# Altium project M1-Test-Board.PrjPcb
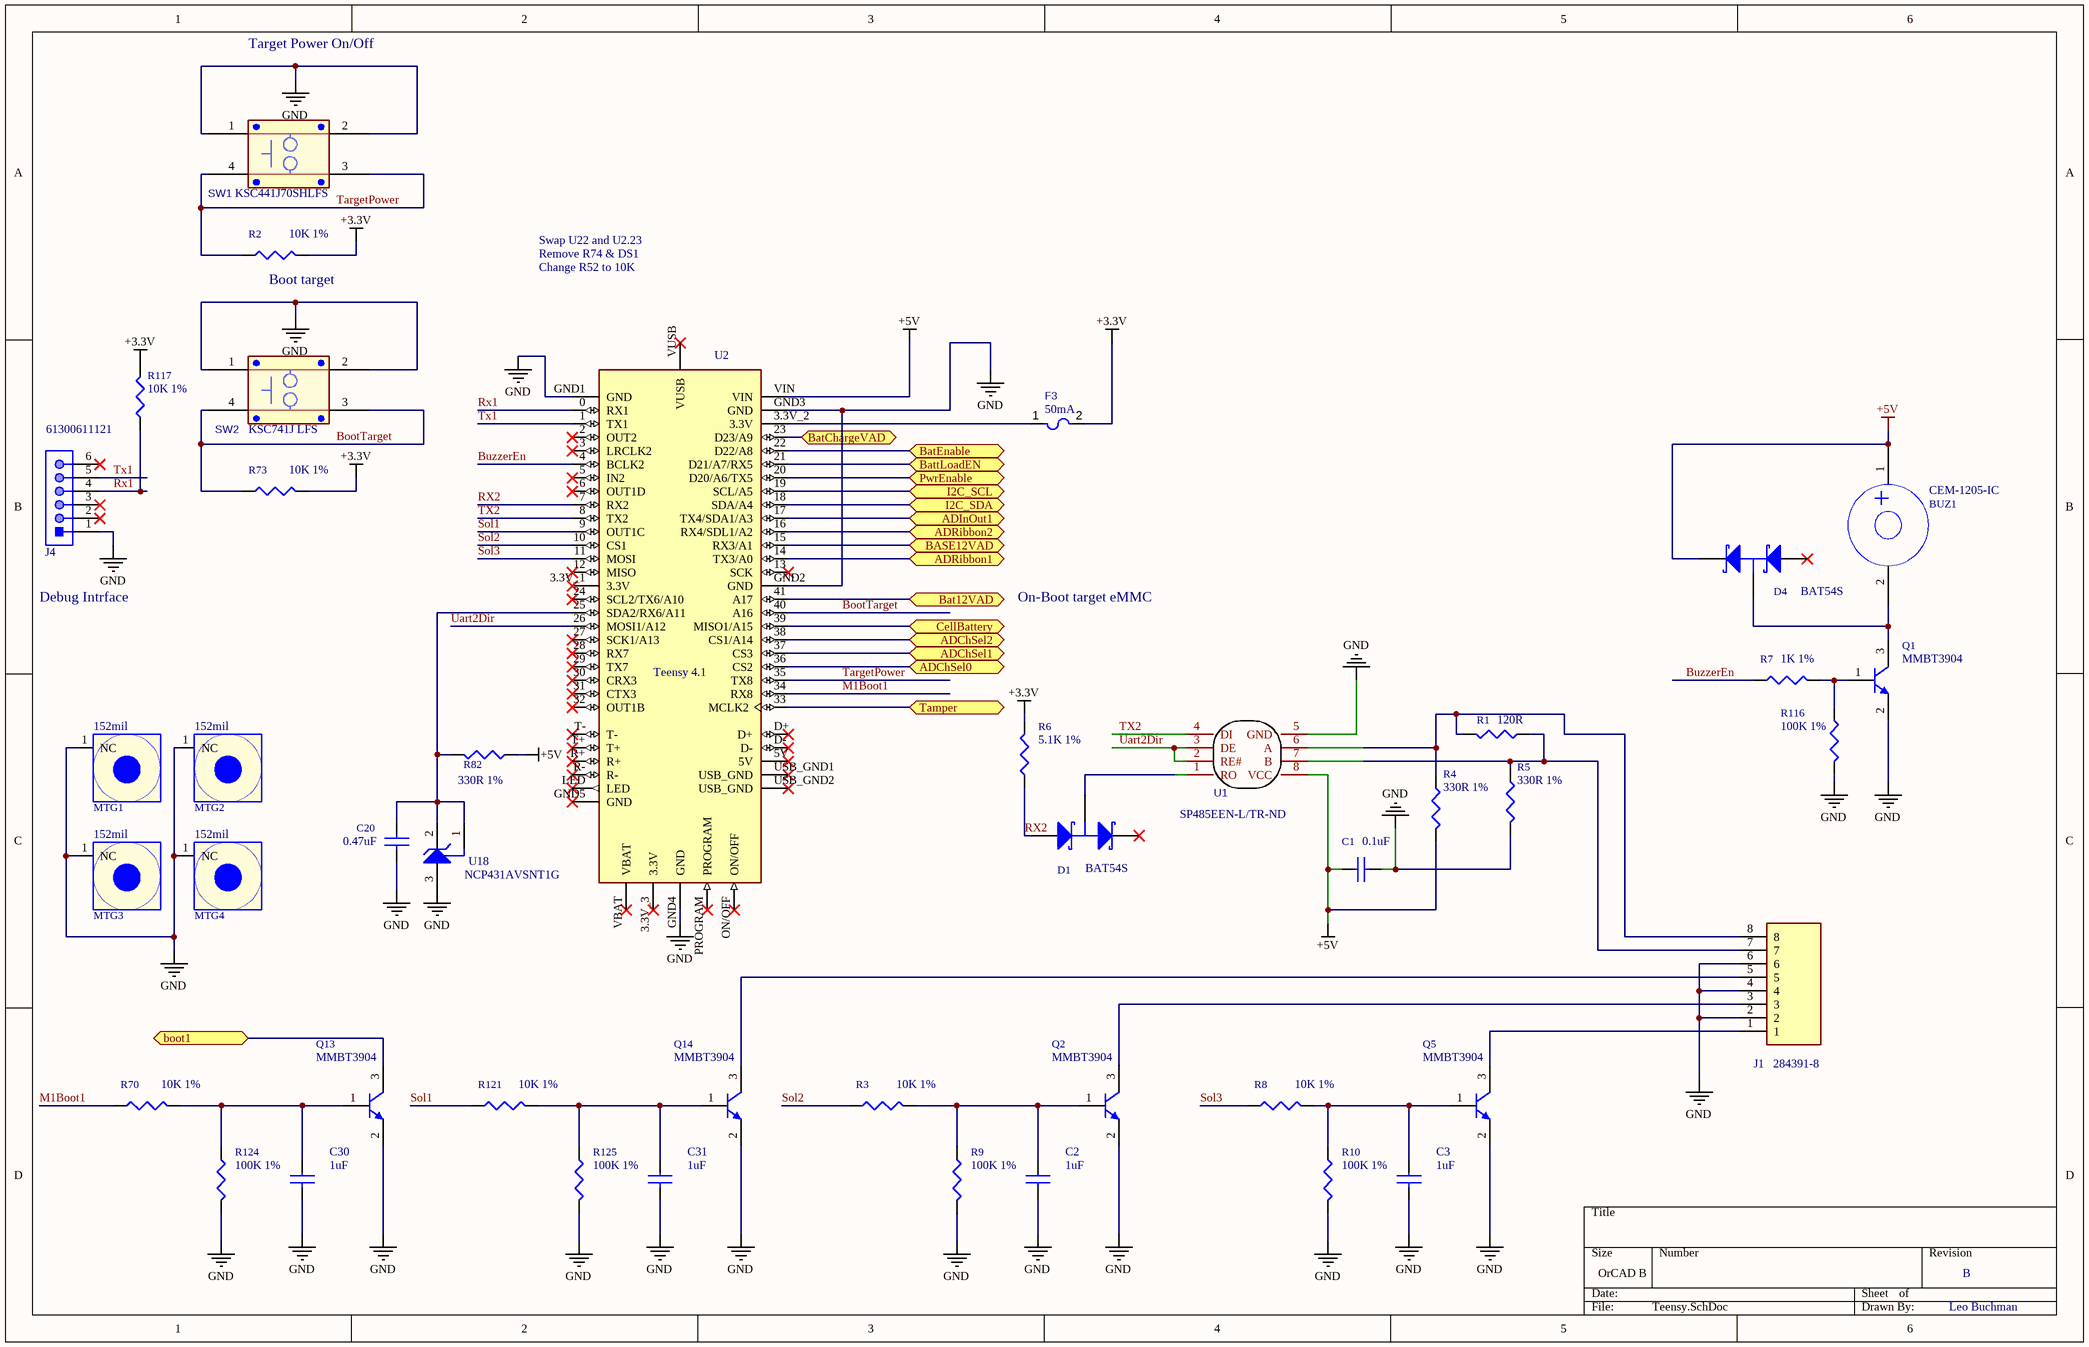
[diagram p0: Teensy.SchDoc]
4 sheets, 191 parts. Net scope: flat (ports and power ports of the same name join across sheets).
Board file: M1-Test-Board.PcbDoc
Sheets:
  Teensy.SchDoc
  RibbonCable.SchDoc
  InputOutput.SchDoc
  Power.SchDoc

## Sheet Teensy.SchDoc: M1 Test Fixture Custom Board
size OrCAD B; Author: Leo Buchman; Revision: B; SheetNumber: 1; SheetTotal: 4

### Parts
BUZ1  CEM-1205-IC  [BUZZ-MB5120C]
C1  0.1uF  [C0402]
C2  1uF  [C0402]
C3  1uF  [C0402]
C20  0.47uF  [C0402]
C30  1uF  [C0402]
C31  1uF  [C0402]
D1  BAT54S  [sot23-3]
D4  BAT54S  [sot23-3]
F3  50mA  [F0603]
J1  284391-8  [TE_284391-8]
J4  61300611121  [61300611121]
MTG1  152mil  [MNT-HOLE-169-350]  (no BOM)
MTG2  152mil  [MNT-HOLE-169-350]  (no BOM)
MTG3  152mil  [MNT-HOLE-169-350]  (no BOM)
MTG4  152mil  [MNT-HOLE-169-350]  (no BOM)
Q1  MMBT3904  [sot23-3]
Q2  MMBT3904  [sot23-3]
Q5  MMBT3904  [sot23-3]
Q13  MMBT3904  [sot23-3]
Q14  MMBT3904  [sot23-3]
R1  120R  [R0402]
R2  10K 1%  [R0402]
R3  10K 1%  [R0402]
R4  330R 1%  [R0402]
R5  330R 1%  [R0402]
R6  5.1K 1%  [R0402]
R7  1K 1%  [R0402]
R8  10K 1%  [R0402]
R9  100K 1%  [R0402]
R10  100K 1%  [R0402]
R70  10K 1%  [R0402]
R73  10K 1%  [R0402]
R82  330R 1%  [R0402]
R116  100K 1%  [R0402]
R117  10K 1%  [R0402]
R121  10K 1%  [R0402]
R124  100K 1%  [R0402]
R125  100K 1%  [R0402]
SW1  KSC441J70SHLFS  [SON4_KSC741JLFS_CNK-red]
SW2  KSC741J LFS  [SON4_KSC741JLFS_CNK-blue]
U1  SP485EEN-L/TR-ND  [NSOIC-8]
U2  Teensy 4.1  [MODULE_DEV-16771 - headers]
U18  NCP431AVSNT1G  [sot23-3]

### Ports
ADChSel0 (bidir), ADChSel1 (bidir), ADChSel2 (bidir), ADInOut1 (bidir), ADRibbon1 (bidir), ADRibbon2 (bidir), BASE12VAD (bidir), Bat12VAD (bidir), BatChargeVAD (bidir), BatEnable (bidir), BattLoadEN (bidir), boot1 (bidir), CellBattery (bidir), I2C_SCL (bidir), I2C_SDA (bidir), PwrEnable (bidir), Tamper (bidir)

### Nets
+3.3V: F3.2 R2.2 R6.2 R73.2 R117.2
+5V: BUZ1.1(POS) C1.1 D4.2(K) R4.2 R82.1 U1.8(VCC) U2.VIN
GND: C1.2 C2.2 C3.2 C20.2 C30.2 C31.2 J1.2 J1.4 J1.6 J4.1 MTG1.1(NC) MTG2.1(NC) MTG3.1(NC) MTG4.1(NC) Q1.2(E) Q2.2(E) Q5.2(E) Q13.2(E) Q14.2(E) R5.2 R9.2 R10.2 R116.2 R124.2 R125.2 SW1.1 SW1.2 SW2.1 SW2.2 U1.5(GND) U2.GND1(GND) U2.GND2(GND) U2.GND3(GND) U2.GND4(GND) U18.3(ANODE)
BootTarget: R73.1 SW2.3 SW2.4 U2.40(A16)
BuzzerEn: R7.1 U2.4(BCLK2)
M1Boot1: R70.1 U2.34(RX8)
Rx1: J4.4 R117.1 U2.0(RX1)
RX2: D1.1(A) R6.1 U2.7(RX2)
Sol1: R121.1 U2.9(OUT1C)
Sol2: R3.1 U2.10(CS1)
Sol3: R8.1 U2.11(MOSI)
TargetPower: R2.1 SW1.3 SW1.4 U2.35(TX8)
Tx1: J4.5 U2.1(TX1)
TX2: U1.4(DI) U2.8(TX2)
Uart2Dir: U1.2(RE#) U1.3(DE) U2.26(MOSI1/A12)
NetBUZ1_2: BUZ1.2(NEG) D4.3(C) Q1.3(C)
NetC2_1: C2.1 Q2.1(B) R3.2 R9.1
NetC3_1: C3.1 Q5.1(B) R8.2 R10.1
NetC20_1: C20.1 R82.2 U2.25(SDA2/RX6/A11) U18.1(REF) U18.2(CATHODE)
NetC22_1: U2.15(RX3/A1) ; port BASE12VAD
NetC23_1: U2.41(A17) ; port Bat12VAD
NetC24_1: U2.23(D23/A9) ; port BatChargeVAD
NetC30_1: C30.1 Q13.1(B) R70.2 R124.1
NetC31_1: C31.1 Q14.1(B) R121.2 R125.1
NetD1_3: D1.3(C) U1.1(RO)
NetF3_1: F3.1 U2.3.3V_2(3.3V)
NetJ1_1: J1.1 Q5.3(C)
NetJ1_3: J1.3 Q2.3(C)
NetJ1_5: J1.5 Q14.3(C)
NetJ1_7: J1.7 R1.1 R5.1 U1.7(B)
NetJ1_8: J1.8 R1.2 R4.1 U1.6(A)
NetJ5_3: U2.18(SDA/A4) ; port I2C_SDA
NetJ5_6: U2.19(SCL/A5) ; port I2C_SCL
NetJ6_8: Q13.3(C) ; port boot1
NetQ1_1: Q1.1(B) R7.2 R116.1
NetR71_2: U2.39(MISO1/A15) ; port CellBattery
NetR85_1: U2.33(MCLK2) ; port Tamper
NetR94_1: U2.20(D20/A6/TX5) ; port PwrEnable
NetR99_1: U2.21(D21/A7/RX5) ; port BattLoadEN
NetR108_1: U2.22(D22/A8) ; port BatEnable
NetR118_1: U2.14(TX3/A0) ; port ADRibbon1
NetR119_1: U2.16(RX4/SDL1/A2) ; port ADRibbon2
NetR120_1: U2.17(TX4/SDA1/A3) ; port ADInOut1
NetU2_36: U2.36(CS2) ; port ADChSel0
NetU2_37: U2.37(CS3) ; port ADChSel1
NetU2_38: U2.38(CS1/A14) ; port ADChSel2

Not connected (* = marked no-connect by the designer): D1 2(K)*; D4 1(A)*; J4 2* 3* 6*; U2 2(OUT2)* 3(LRCLK2)* 3.3V_1(3.3V)* 3.3V_3(3.3V)* 5(IN2)* 5V* 6(OUT1D)* 12(MISO)* 13(SCK)* 24(SCL2/TX6/A10)* 27(SCK1/A13)* 28(RX7)* 29(TX7)* 30(CRX3)* 31(CTX3)* 32(OUT1B)* D+* D-* GND5(GND)* LED* ON/OFF* PROGRAM* R+* R-* T+* T-* USB_GND1(USB_GND)* USB_GND2(USB_GND)* VBAT* VUSB*

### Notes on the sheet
- Target Power On/Off
- (near R2) Boot target
- Swap U22 and U2.23
- Remove R74 & DS1
- Change R52 to 10K
- Debug Intrface
- On-Boot target eMMC

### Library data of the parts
BUZ1 = Mod-0003: 12 mm, 5 Vdc, 92 dB, Through Hole, Driving Circuit, Magnetic Audio Indicator Buzzer; ADI Part Number: 3716-0001; Manufacturer: CUI Devices; Voltage: 5V; Current: 35mA; CLASS: DISCRETE; COMPSIDE: TOP; COMPLOC: [1301.000,1659.000]; COMPROT: 180; COMPGROUP: 0; COMPFIXED: NO; COMPHEIGHT: 0.000
C1 = Cap-00005: Cap Ceramic 0.1uF 50V X7R 10% Pad SMD 0402 125C Automotive T/R; Manufacturer: Murata; Manufacturer Part Number: GRT155R71H104KE01D
C2 C3 C30 C31 = Cap-00003: CAP CER 1UF 10V Y5V 0402; Manufacturer: KEMET; Manufacturer Part Number: C0402C105Z8VAC7867; Tolerance: 80%; Dielectric Material: Ceramic
C20 = Cap-00006: CAP CER 0.47UF 16V Y5V 0402; Manufacturer: Yageo; Manufacturer Part Number: CC0402ZRY5V7BB474; Tolerance: 80%; Capacitance: 470nF; Dielectric Material: Ceramic
D1 D4 = Diode-0009: DIODE SCHOTTKY 30V 150MA SOT23-3; Manufacturer: Sangdest Microelectronics; Manufacturer: ON Semiconductor / Fairchild; Recovery Time: 5ns; Package Version: Rev. 12, 03/2016; Peak Reverse Current: 2uA; Elements: 2
F3 = FEMTOASMDC005F-2: Ptc Reset Fuse 15V 50MA 0603; Manufacturer: Littelfuse; Manufacturer: Bourns; Max Current Rating: 10A; Trip Current: 150mA; Time to Trip: 100ms
J1 = CON-0011: Conn Terminal Block F 8 POS 3.5mm Solder ST T; MF: TE Connectivity
J4 = CON-0003: CONN HEADER 6 POS 2.54; Manufacturer: Wurth Electronics
MTG1-MTG4 = Hole-001: Plated
Q1 Q2 Q5 Q13 Q14 = Tran-0002: Trans GP BJT NPN 60V 0.2A 350mW Automotive 3-Pin SOT-23 T/R; Manufacturer: ON Semiconductor / Fairchild; Manufacturer: ON Semiconductor; Elements: 1; Power: 225mW; Frequency: 250MHz; Vce Max: 300mV; Max Collector Current: 200mA; Collector-emitter Voltage-Max: 400mV
R1 = Res-00013: Res Thick Film 0402 120 Ohm 1% 0.063W(1/16W) ±100ppm/C Pad SMD Automotive T/R; Manufacturer: Stackpole Electronics; Manufacturer Part Number: RMCF0402FT120R; Max Power Dissipation: 63mW; Temperature Coefficient: 100ppm/°C
R2 R3 R8 R70 R73 R117 R121 = Res-00002: Thick Film 0402 10K OHM 1% 1/16W 0402; Manufacturer: Yageo; Manufacturer Part Number: RC0402FR-0710KP; Max Power Dissipation: 63mW; Temperature Coefficient: 150ppm/°C; Power Rating: 62.5mW
R4 R5 R82 = Res-00009: Thick Film 0402 330 Ohm 1% 1/16W ±100ppm/°C Molded SMD Paper T/R; Manufacturer: Yageo; Manufacturer Part Number: AF0402FR-07330RL; Max Power Dissipation: 63mW; Power Rating: 62.5mW
R6 = Res-00004: Thick Film 0402 5.1K Ohm 1% 1/16W 0402; Manufacturer: Stackpole Electronics; Manufacturer Part Number: RMCF0402FT5K10; Max Power Dissipation: 63mW; Temperature Coefficient: 100ppm/°C; Power Rating: 62.5mW
R7 = Res-00001: Thick Film 0402 1K Ohm 1% 1/8W 0402; Manufacturer: TE Connectivity; Manufacturer Part Number: CRGP0402F1K0; Max Power Dissipation: 125mW; Temperature Coefficient: 100ppm/°C; Power Rating: 0.125W
R9 R10 R116 R124 R125 = Res-00003: Thick Film 0402 100K OHM 1% 1/16W 0402; Manufacturer: Stackpole Electronics; Manufacturer Part Number: RMCF0402FT100K; Power Rating: 62.5mW
SW1 = SW-0002: Switch Tactile N.O. SPST Round Button J-Bend; Manufacturer: ITT C&K; Actuator Material: Nylon,Polyamide,PA66; Mechanical Life: 300000Cycles; Operating Force: 5N; Max Current Rating: 50mA; Voltage Rating (DC): 32V; Illumination Type: Non-Illuminated,Illuminated; Switch Function: Off-Mom; Actuator Type: Standard; Switch Travel: 0.75mm; Actuator Length: 2.6mm; Power Rating: 1W
SW2 = SW-0001: Switch Tactile N.O. SPST Round Button J-Bend; Manufacturer: ITT C&K; Mechanical Life: 300000Cycles; Actuator Color: Blue; Operating Force: 4N; Max Current Rating: 50mA; Voltage Rating (DC): 32V; Illumination Type: Non-Illuminated; Switch Function: Off-Mom; Actuator Type: Standard; Switch Travel: 0.4mm; Actuator Length: 1.7mm; Power Rating: 1W; Ratings: IP67,Waterproof,Dust Tight
U1 = dd-0001: IC TXRX RS485 HALF DUPLEX 8SOIC; BOM_Manufacturer: EXAR; Package Display: No; Data Rate: 10Mbps; Nominal Supply Current: 900uA; Max Power Dissipation: 550mW; Operating Supply Voltage: 5V; Number of Receivers: 1; Min Supply Voltage: 4.75V; Max Supply Voltage: 5.25V; Logic Function: Transceiver; Interface: RS-422,RS-485
U2 = Mod-0004: Teensy 4.1 Development Board; Manufacturer: SparkFun
U18 = AIC-0002: V-Ref Adjustable 2.5V to 36V 100mA 3-Pin SOT-; Manufacturer: ON Semiconductor; PartNumber: TL431ACLP; Manufacturer: Texas Instruments; VO Adj(Max)(V): 36; Initial Accuracy @ 25/deg C(%): 1; SubFamily: Shunt Voltage Reference; Temp Coeff(Typ)(ppm/ degree C): 34; VO Adj(Min)(V): 2.495; Rating: Catalog; Min Iz for Regulation(uA): 600; Temp Coeff(Max)(ppm/ degree C): 92; Iout/Iz(Max)(mA): 100; Eco-Plan: Pb-Free (RoHS); Max Input Voltage: 2.525V; Min Input Voltage: 2.475V; Tolerance: 1%; Temperature Coefficient: 50ppm/°C; Cathode Current: 60uA; Reference Type: Shunt,Adjustable,Programmable

## Sheet RibbonCable.SchDoc: M1 Test Fixture Custom Board
size OrCAD B; Author: Leo Buchman; Revision: B; SheetNumber: 2; SheetTotal: 4
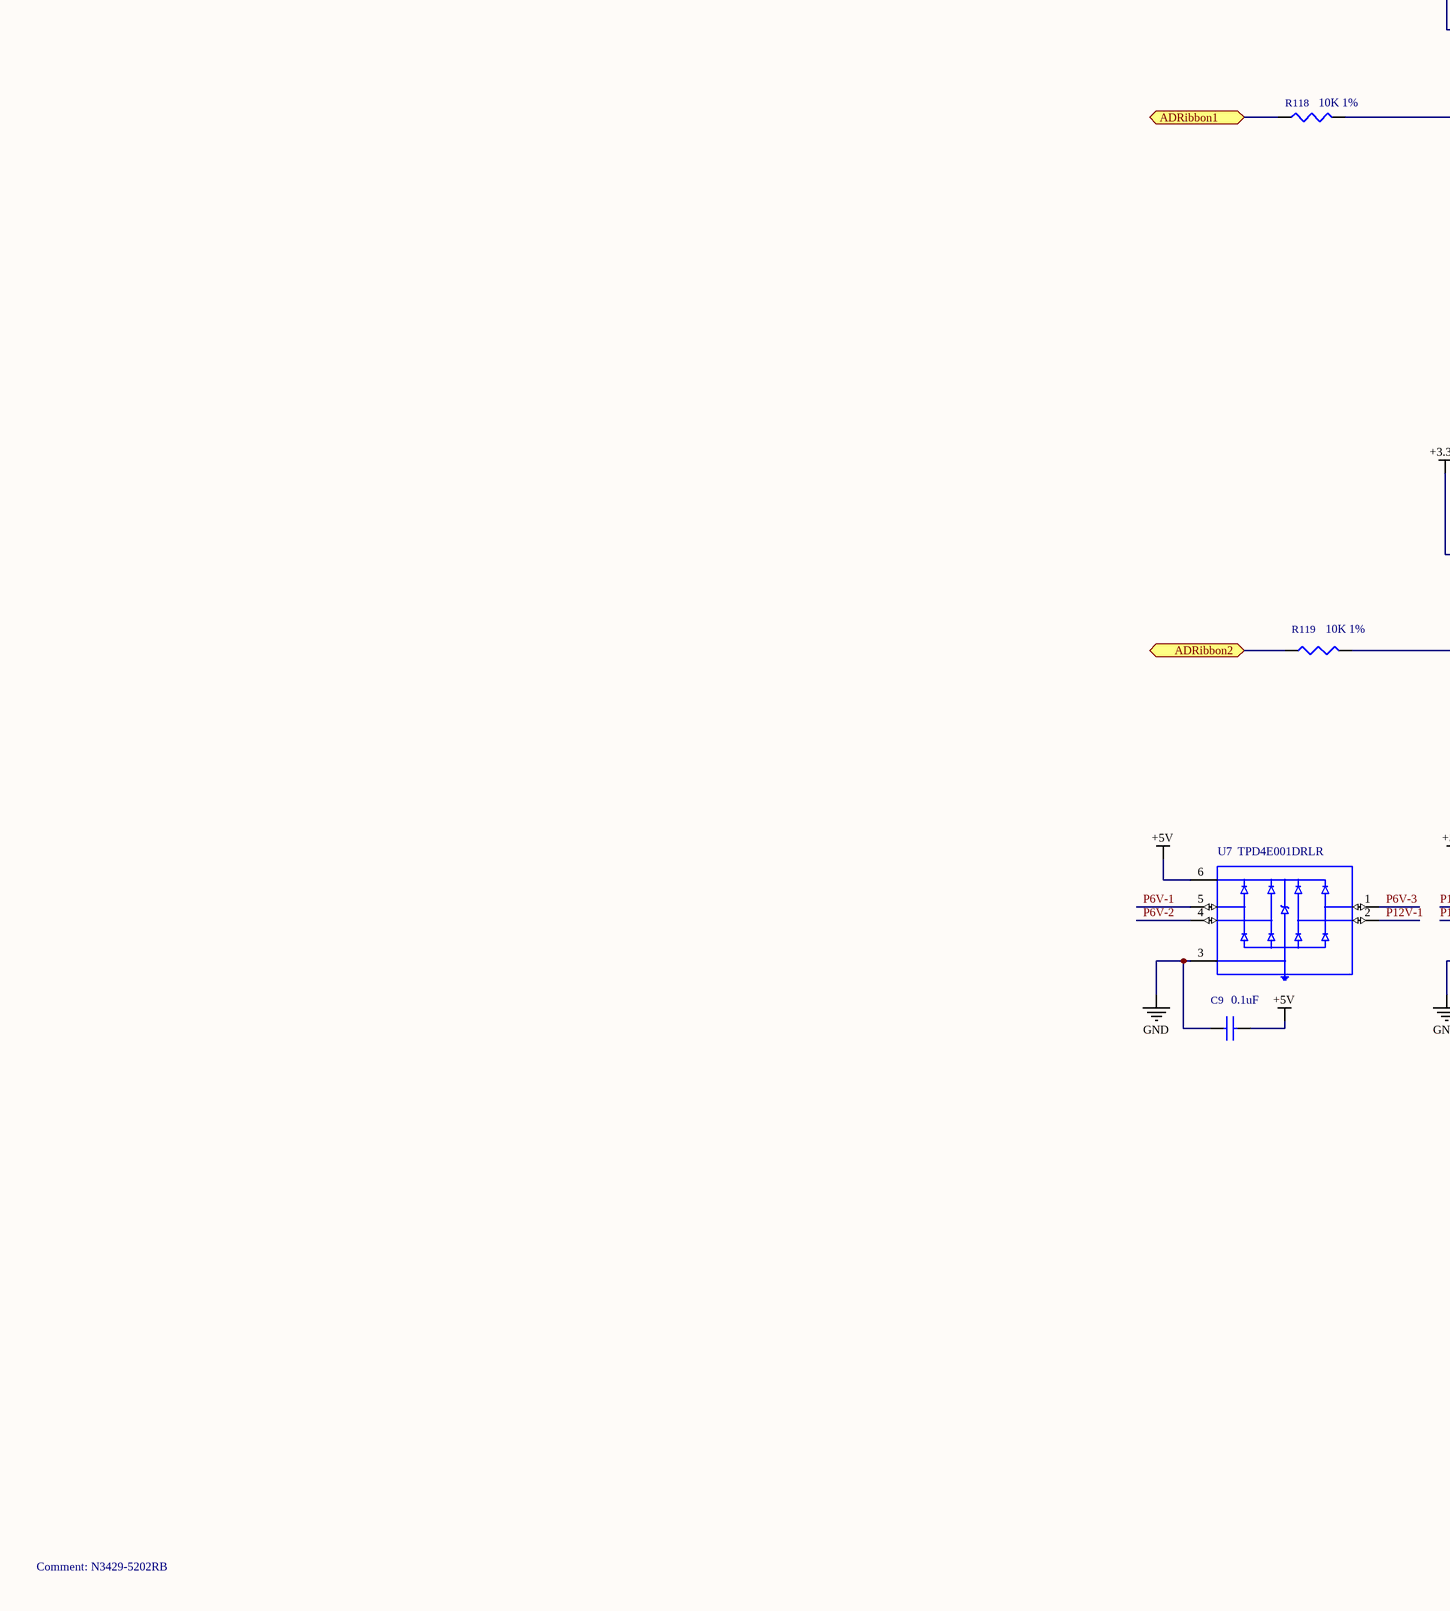
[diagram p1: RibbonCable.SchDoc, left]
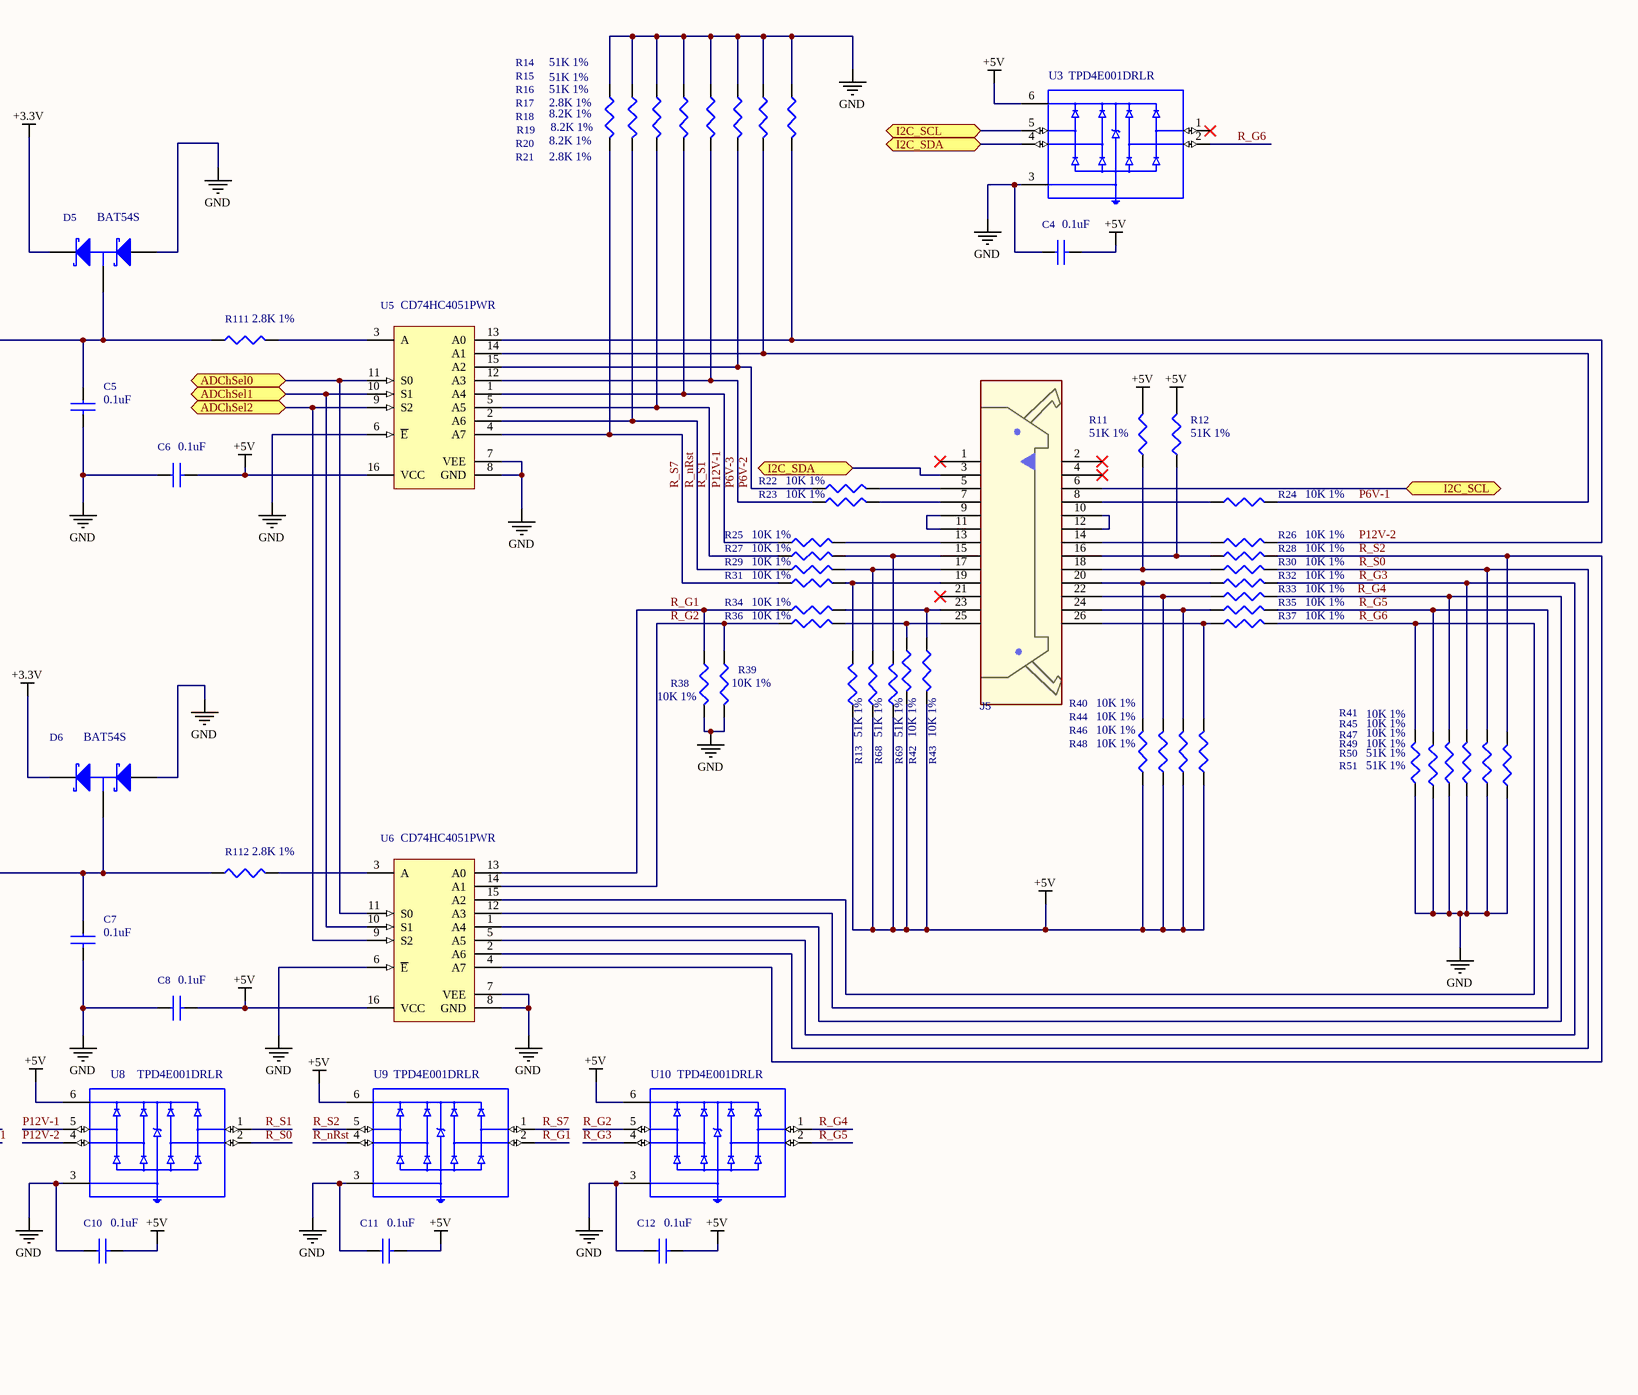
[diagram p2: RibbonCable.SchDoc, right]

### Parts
C4  0.1uF  [C0402]
C5  0.1uF  [C0402]
C6  0.1uF  [C0402]
C7  0.1uF  [C0402]
C8  0.1uF  [C0402]
C9  0.1uF  [C0402]
C10  0.1uF  [C0402]
C11  0.1uF  [C0402]
C12  0.1uF  [C0402]
D5  BAT54S  [sot23-3]
D6  BAT54S  [sot23-3]
J5  N3429-5202RB  [CONN_N3429-5202RB]
R11  51K 1%  [R0402]
R12  51K 1%  [R0402]
R13  51K 1%  [R0402]
R14  51K 1%  [R0402]
R15  51K 1%  [R0402]
R16  51K 1%  [R0402]
R17  2.8K 1%  [R0402]
R18  8.2K 1%  [R0402]
R19  8.2K 1%  [R0402]
R20  8.2K 1%  [R0402]
R21  2.8K 1%  [R0402]
R22  10K 1%  [R0402]
R23  10K 1%  [R0402]
R24  10K 1%  [R0402]
R25  10K 1%  [R0402]
R26  10K 1%  [R0402]
R27  10K 1%  [R0402]
R28  10K 1%  [R0402]
R29  10K 1%  [R0402]
R30  10K 1%  [R0402]
R31  10K 1%  [R0402]
R32  10K 1%  [R0402]
R33  10K 1%  [R0402]
R34  10K 1%  [R0402]
R35  10K 1%  [R0402]
R36  10K 1%  [R0402]
R37  10K 1%  [R0402]
R38  10K 1%  [R0402]
R39  10K 1%  [R0402]
R40  10K 1%  [R0402]
R41  10K 1%  [R0402]
R42  10K 1%  [R0402]
R43  10K 1%  [R0402]
R44  10K 1%  [R0402]
R45  10K 1%  [R0402]
R46  10K 1%  [R0402]
R47  10K 1%  [R0402]
R48  10K 1%  [R0402]
R49  10K 1%  [R0402]
R50  51K 1%  [R0402]
R51  51K 1%  [R0402]
R68  51K 1%  [R0402]
R69  51K 1%  [R0402]
R111  2.8K 1%  [R0402]
R112  2.8K 1%  [R0402]
R118  10K 1%  [R0402]
R119  10K 1%  [R0402]
U3  TPD4E001DRLR  [SOTFL50P160X60-6N]
U5  CD74HC4051PWR  [16-TSSOP-4.4mm]
U6  CD74HC4051PWR  [16-TSSOP-4.4mm]
U7  TPD4E001DRLR  [SOTFL50P160X60-6N]
U8  TPD4E001DRLR  [SOTFL50P160X60-6N]
U9  TPD4E001DRLR  [SOTFL50P160X60-6N]
U10  TPD4E001DRLR  [SOTFL50P160X60-6N]

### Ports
ADChSel0 (bidir), ADChSel1 (bidir), ADChSel2 (bidir), ADRibbon1 (bidir), ADRibbon2 (bidir), I2C_SCL (bidir), I2C_SDA (bidir)

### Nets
+3.3V: D5.2(K) D6.2(K)
+5V: C4.2 C6.2 C8.2 C9.2 C10.2 C11.2 C12.2 R11.2 R12.2 R13.1 R40.1 R42.2 R43.2 R44.1 R46.1 R48.1 R68.1 R69.1 U3.6(VCC) U5.16(VCC) U6.16(VCC) U7.6(VCC) U8.6(VCC) U9.6(VCC) U10.6(VCC)
GND: C4.1 C5.2 C6.1 C7.2 C8.1 C9.1 C10.1 C11.1 C12.1 D5.1(A) D6.1(A) R14.1 R15.1 R16.1 R17.1 R18.1 R19.1 R20.1 R21.1 R38.2 R39.2 R41.1 R45.1 R47.1 R49.1 R50.1 R51.1 U3.3(GND) U5.6(~{E}) U5.7(VEE) U5.8(GND) U6.6(~{E}) U6.7(VEE) U6.8(GND) U7.3(GND) U8.3(GND) U9.3(GND) U10.3(GND)
P6V-1: R20.2 R24.2 U5.14(A1) U7.5(IO4)
P6V-2: R19.2 R22.1 U5.15(A2) U7.4(IO3)
P6V-3: R18.2 R23.1 U5.12(A3) U7.1(IO1)
P12V-1: R17.2 R25.1 U5.1(A4) U7.2(IO2) U8.5(IO4)
P12V-2: R21.2 R26.2 U5.13(A0) U8.4(IO3)
R_G1: R34.1 R38.1 U6.13(A0) U9.2(IO2)
R_G2: R36.1 R39.1 U6.14(A1) U10.5(IO4)
R_G3: R32.2 R49.2 U6.5(A5) U10.4(IO3)
R_G4: R33.2 R47.2 U6.1(A4) U10.1(IO1)
R_G5: R35.2 R45.2 U6.12(A3) U10.2(IO2)
R_G6: R37.2 R41.2 U3.2(IO2) U6.15(A2)
R_nRst: R15.2 R29.1 U5.2(A6) U9.4(IO3)
R_S0: R30.2 R50.2 U6.2(A6) U8.2(IO2)
R_S1: R16.2 R27.1 U5.5(A5) U8.1(IO1)
R_S2: R28.2 R51.2 U6.4(A7) U9.5(IO4)
R_S7: R14.2 R31.1 U5.4(A7) U9.1(IO1)
NetC5_1: C5.1 D5.3(C) R111.1 R118.2
NetC7_1: C7.1 D6.3(C) R112.1 R119.2
NetJ5_3: J5.3 U3.4(IO3) ; port I2C_SDA
NetJ5_5: J5.5 R22.2
NetJ5_6: J5.6 U3.5(IO4) ; port I2C_SCL
NetJ5_7: J5.7 R23.2
NetJ5_8: J5.8 R24.1
NetJ5_9: J5.9 J5.11
NetJ5_10: J5.10 J5.12
NetJ5_13: J5.13 R25.2
NetJ5_14: J5.14 R26.1
NetJ5_15: J5.15 R27.2 R69.2
NetJ5_16: J5.16 R12.1 R28.1
NetJ5_17: J5.17 R29.2 R68.2
NetJ5_18: J5.18 R11.1 R30.1
NetJ5_19: J5.19 R13.2 R31.2
NetJ5_20: J5.20 R32.1 R40.2
NetJ5_22: J5.22 R33.1 R44.2
NetJ5_23: J5.23 R34.2 R43.1
NetJ5_24: J5.24 R35.1 R46.2
NetJ5_25: J5.25 R36.2 R42.1
NetJ5_26: J5.26 R37.1 R48.2
NetR111_2: R111.2 U5.3(A)
NetR112_2: R112.2 U6.3(A)
NetR118_1: R118.1 ; port ADRibbon1
NetR119_1: R119.1 ; port ADRibbon2
NetU2_36: U5.11(S0) U6.11(S0) ; port ADChSel0
NetU2_37: U5.10(S1) U6.10(S1) ; port ADChSel1
NetU2_38: U5.9(S2) U6.9(S2) ; port ADChSel2

Not connected (* = marked no-connect by the designer): J5 1* 2* 4* 21*; U3 1(IO1)*

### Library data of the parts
C4-C12 = Cap-00005: as C1 on sheet Teensy
D5 D6 = Diode-0009: as D1 on sheet Teensy
J5 = CON-0010: 3000 Series; 2.54mm Pitch 26 Way 2 Row Right; Manufacturer: 3M; ATTR: CONN HEADER LATCH/EJEC  RTA DUAL ROW 26POS; PKG: 2M54_13x2_TH_LATCH; Connector Type: Male Pin; Number of Positions: 26; Current Rating: 1A; Voltage Rating: 300V; Gender: Male; Number of Positions Per Level: 8; Number of Levels: 1; Max Current Rating: 2A; Current: 12A; Shrouded: Yes (With); Tail Length: 3.5mm; Wire Gauge (Max): 30AWG; Row Spacing: 0.1inch; Closed End: No (Without); Plating: Brass; Thread Size: M2
R11-R16 R50 R51 R68 R69 = Res-00011: Res Thick Film 0402 51K Ohm 1% 0.063W(1/16W) ±100ppm/C Pad SMD Automotive T/R; Manufacturer: Stackpole Electronics; Manufacturer Part Number: RMCF0402FT51K0; Resistance: 51kR; Max Power Dissipation: 63mW; Temperature Coefficient: 100ppm/°C
R17 R21 R111 R112 = Res-00008: Thick Film 0402 2.8K Ohm 1% 0.063W ±100ppm/°C Molded SMD Paper T/R; Manufacturer: Stackpole Electronics; Manufacturer Part Number: RMCF0402FT2K80; Resistance: 2.8kR; Max Power Dissipation: 63mW; Power Rating: 62.5mW
R18-R20 = Res-00012: Res Thick Film 0402 8.2K Ohm 5% 0.063W ±100ppm/°C Molded SMD Paper T/R; Manufacturer: Stackpole Electronics; Manufacturer Part Number: RMCF0402JT8K20; Resistance: 8.2kR; Max Power Dissipation: 63mW
R22-R49 R118 R119 = Res-00002: as R2 on sheet Teensy
U3 U7-U10 = Diode-0012: TVS DIODE 5.5VWM SOT6; Manufacturer: Texas Instruments; Capacitance: 1.5pF; Max Power Dissipation: 100W; Breakdown Voltage: 11V; Direction: Unidirectional; Reverse Standoff Voltage: 5.5V; Clamping Voltage: 105.5V; Power Line Protection: Yes; Number of Channels: 4; Leakage Current: 1nA; Peak Pulse Current: 5.5A; Interface: LVDS,USB,Ethernet
U5 U6 = AIC-0001: 5-V, 8: 1, 1-channel analog mutliplexer 16-TS; Manufacturer: Texas Instruments; VCC(Max)(V): 6; Ron(Typ)(Ohms): 45; Rating: Catalog; VCC(Min)(V): 2; Ron(Max)(Ohms): 130; Configuration: 1 X 1：8 MUX; Crosstalk: Yes; Bandwidth(Max)(MHz): 180; Bandwidth: 180MHz; Propagation Delay: 60ns; Number of Outputs: 1; Max Supply Voltage: 6V; Min Supply Voltage: 2V; Number of Inputs: 8; Min Dual Supply Voltage: 1V; Max Dual Supply Voltage: 5V; Dual Supply Voltage: 3V; Logic Function: Multiplexer,Demultiplexer; On-State Resistance: 130R; Turn-On Delay Time: 225ns; Supply Type: Single,Dual; Nominal Supply Current: 16uA; Polarity: Non-Inverting; Low Level Output Current: 25mA

## Sheet InputOutput.SchDoc: M1 Test Fixture Custom Board
size OrCAD B; Author: Leo Buchman; Revision: B; SheetNumber: 3; SheetTotal: 4
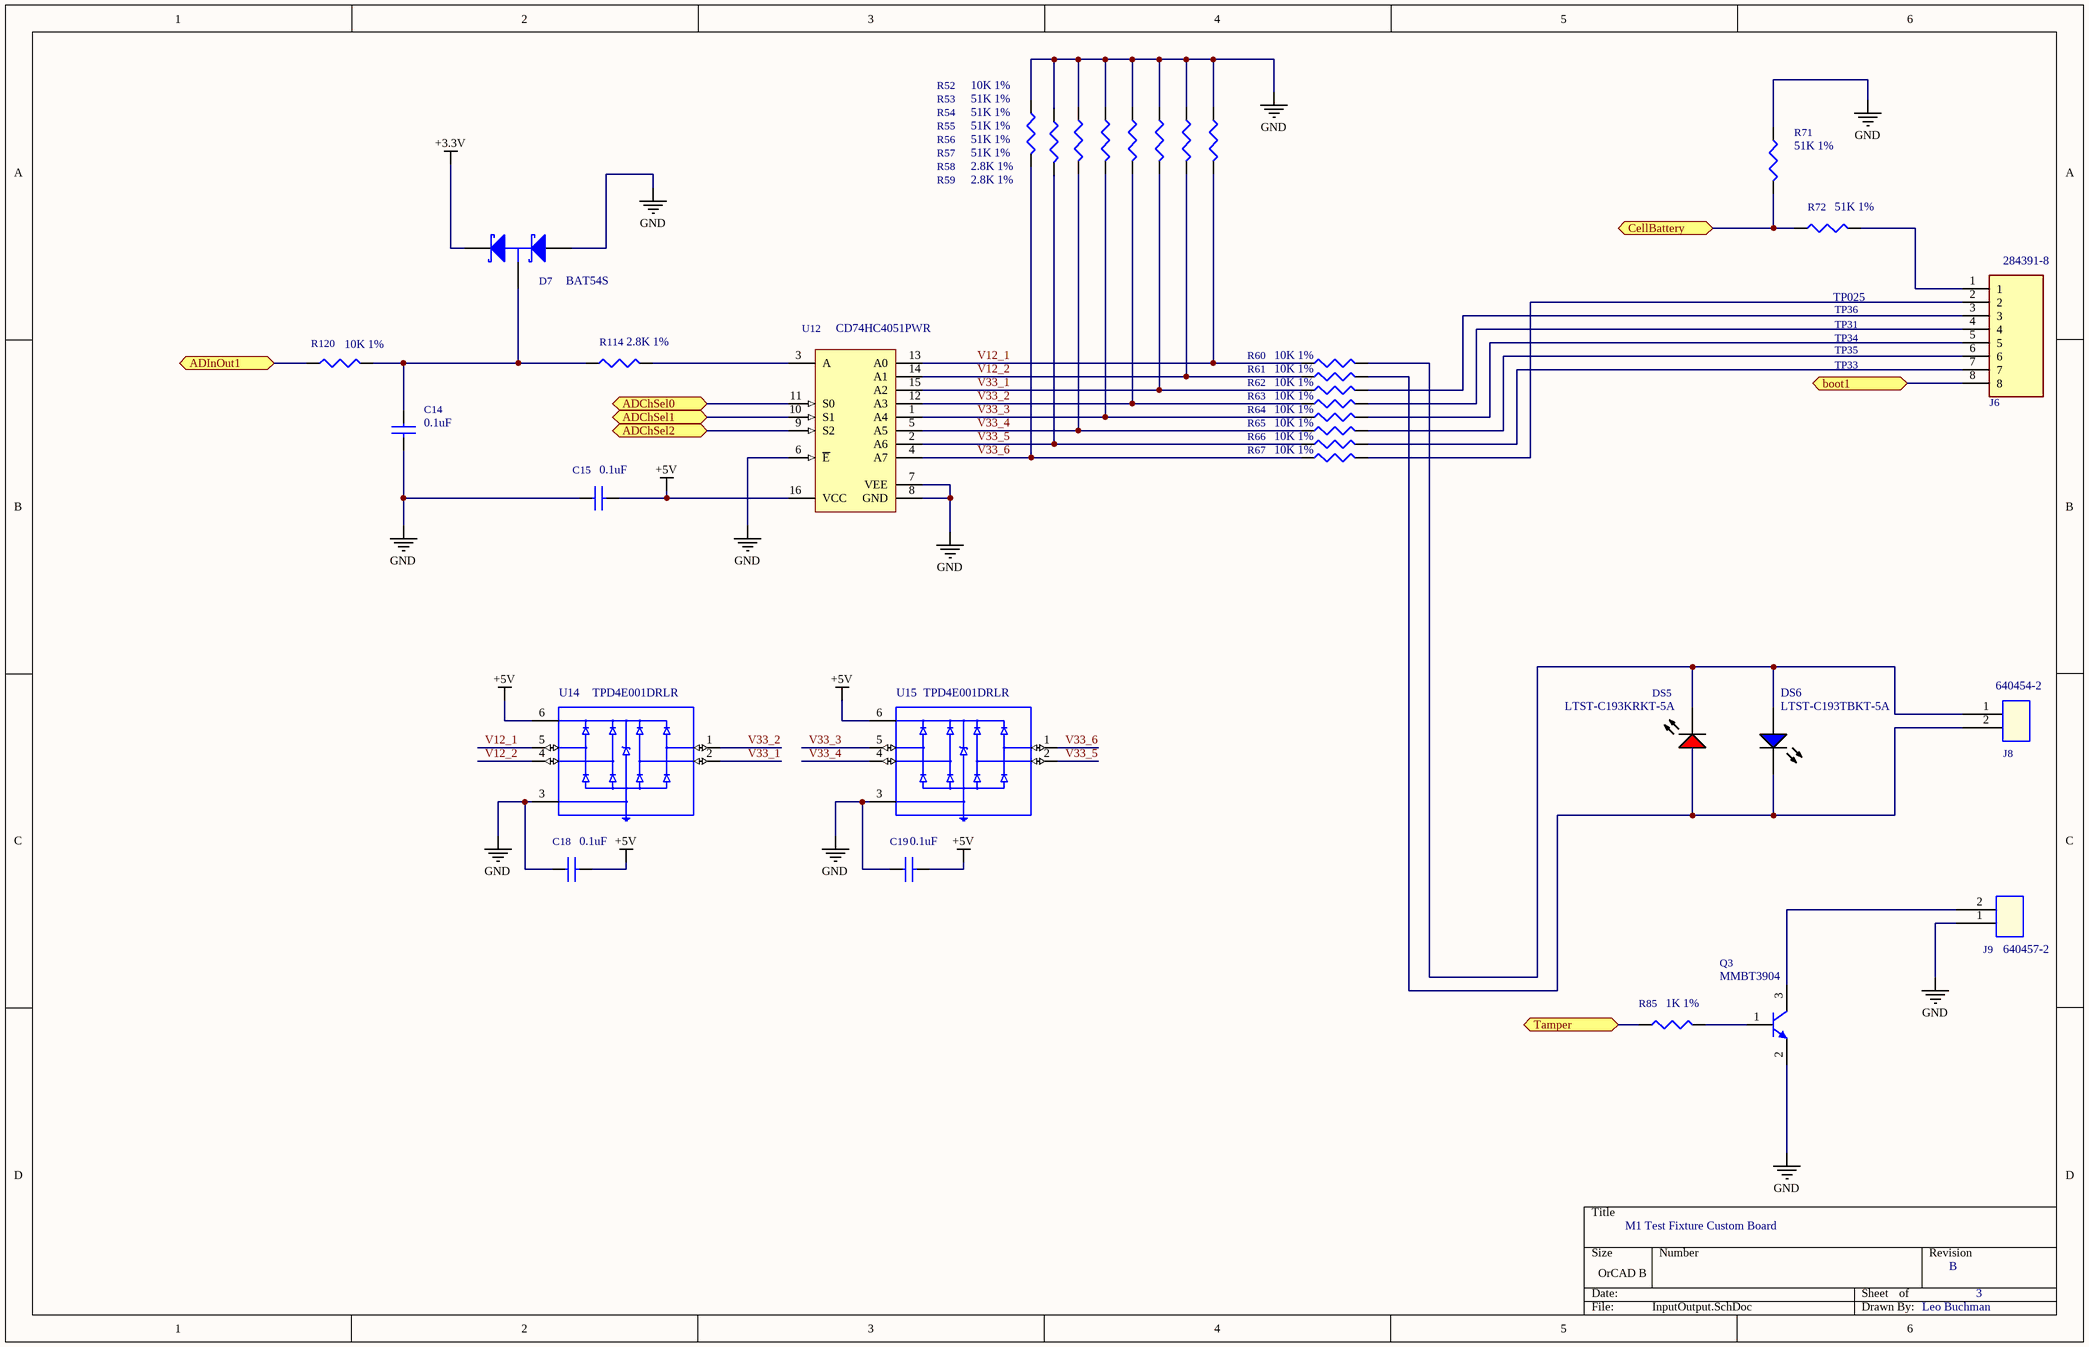
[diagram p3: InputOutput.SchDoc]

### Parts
C14  0.1uF  [C0402]
C15  0.1uF  [C0402]
C18  0.1uF  [C0402]
C19  0.1uF  [C0402]
D7  BAT54S  [sot23-3]
DS5  LTST-C193KRKT-5A  [LED-RED_0603]
DS6  LTST-C193TBKT-5A  [LED-BLUE_0603]
J6  284391-8  [TE_284391-8]
J8  640454-2  [CON$5C$2P$5C$100LM]
J9  640457-2  [TE_640457-2]
Q3  MMBT3904  [sot23-3]
R52  10K 1%  [R0402]
R53  51K 1%  [R0402]
R54  51K 1%  [R0402]
R55  51K 1%  [R0402]
R56  51K 1%  [R0402]
R57  51K 1%  [R0402]
R58  2.8K 1%  [R0402]
R59  2.8K 1%  [R0402]
R60  10K 1%  [R0402]
R61  10K 1%  [R0402]
R62  10K 1%  [R0402]
R63  10K 1%  [R0402]
R64  10K 1%  [R0402]
R65  10K 1%  [R0402]
R66  10K 1%  [R0402]
R67  10K 1%  [R0402]
R71  51K 1%  [R0402]
R72  51K 1%  [R0402]
R85  1K 1%  [R0402]
R114  2.8K 1%  [R0402]
R120  10K 1%  [R0402]
U12  CD74HC4051PWR  [16-TSSOP-4.4mm]
U14  TPD4E001DRLR  [SOTFL50P160X60-6N]
U15  TPD4E001DRLR  [SOTFL50P160X60-6N]

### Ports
ADChSel0 (bidir), ADChSel1 (bidir), ADChSel2 (bidir), ADInOut1 (bidir), boot1 (bidir), CellBattery (bidir), Tamper (bidir)

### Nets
+3.3V: D7.2(K)
+5V: C15.2 C18.2 C19.2 U12.16(VCC) U14.6(VCC) U15.6(VCC)
GND: C14.2 C15.1 C18.1 C19.1 D7.1(A) J9.1 Q3.2(E) R52.1 R53.1 R54.1 R55.1 R56.1 R57.1 R58.1 R59.1 R71.1 U12.6(~{E}) U12.7(VEE) U12.8(GND) U14.3(GND) U15.3(GND)
V12_1: R59.2 R60.1 U12.13(A0) U14.5(IO4)
V12_2: R58.2 R61.1 U12.14(A1) U14.4(IO3)
V33_1: R57.2 R62.1 U12.15(A2) U14.2(IO2)
V33_2: R56.2 R63.1 U12.12(A3) U14.1(IO1)
V33_3: R55.2 R64.1 U12.1(A4) U15.5(IO4)
V33_4: R54.2 R65.1 U12.5(A5) U15.4(IO3)
V33_5: R53.2 R66.1 U12.2(A6) U15.2(IO2)
V33_6: R52.2 R67.1 U12.4(A7) U15.1(IO1)
NetC14_1: C14.1 D7.3(C) R114.1 R120.2
NetDS5_1: DS5.1(A) DS6.2(K) J8.2 R61.2
NetDS5_2: DS5.2(K) DS6.1(A) J8.1 R60.2
NetJ6_1: J6.1 R72.2
NetJ6_2: J6.2 R67.2
NetJ6_3: J6.3 R62.2
NetJ6_4: J6.4 R63.2
NetJ6_5: J6.5 R64.2
NetJ6_6: J6.6 R65.2
NetJ6_7: J6.7 R66.2
NetJ6_8: J6.8 ; port boot1
NetJ9_2: J9.2 Q3.3(C)
NetQ3_1: Q3.1(B) R85.2
NetR71_2: R71.2 R72.1 ; port CellBattery
NetR85_1: R85.1 ; port Tamper
NetR114_2: R114.2 U12.3(A)
NetR120_1: R120.1 ; port ADInOut1
NetU2_36: U12.11(S0) ; port ADChSel0
NetU2_37: U12.10(S1) ; port ADChSel1
NetU2_38: U12.9(S2) ; port ADChSel2

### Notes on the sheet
- TP025
- TP36
- TP31
- TP34
- TP35
- TP33

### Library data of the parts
C14 C15 C18 C19 = Cap-00005: as C1 on sheet Teensy
D7 = Diode-0009: as D1 on sheet Teensy
DS5 = Diode-0005: LED RED CLEAR 0603 SMD; Manufacturer: Vishay Lite-On; Manufacturer: Broadcom Avago; Type: Uni-Color; Product Height (mm): 1.1mm; Power Dissipation: 50mW; Product Length (mm): 3.2mm; Forward Voltage: 2.0V; Luminous Intensity: 45mcd; DELETED: Compliant; Shape Type: Rectangular; Peak Wavelength: 660nm; Main Category: ChipLED; Dominant Wave Length: 639nm; Rad Hardened: No; Lens Type: ColorlessDiffused; Product Depth (mm): 1.6mm; Reverse Voltage: 5V; Forward Current: 5mA; Chip Material: GaAlAs; Test Current (It): 20mA; Lum Intensity: 17mcd; Viewing Angle: 130°; Number of  Elements: 1; Lens Style: Diffused,Colorless,Clear,Rectangular; Dominant Wavelength: 631nm; Lens Color: Colorless
DS6 = Diode-0003: LED Blue CLEAR 0603 SMD; Manufacturer: Vishay Lite-On; Manufacturer: Rohm; Viewing Angle: 130°; Forward Voltage: 2.8V; Forward (Drive) Current: 20mA; Intensity: 22mcd; Lens Style: Diffused,Colorless,Rectangular,Clear; Luminous Intensity: 15mcd; Dominant Wavelength: 475nm; Number of Elements: 1; Power Dissipation: 76mW; Test Current: 5mA; Reverse Voltage: 5V; Lens Color: Colorless
J6 = CON-0011: as J1 on sheet Teensy
J8 = CON-0013: Header, Polarized; MTA-100; 2; 250 VAC; Polye; Manufacturer: TE Connectivity; Parameter 1: C86502
J9 = CON-0014: MTA-100 HEADER  Friction Lock R/A 2POS 2.54MM; Manufacturer: AMP - TE CONNECTIVITY; Parameter 1: C86502
Q3 = Tran-0002: as Q1 on sheet Teensy
R52 R60-R67 R120 = Res-00002: as R2 on sheet Teensy
R53-R57 R71 R72 = Res-00011: as R11 on sheet RibbonCable
R58 R59 R114 = Res-00008: as R17 on sheet RibbonCable
R85 = Res-00001: as R7 on sheet Teensy
U12 = AIC-0001: as U5 on sheet RibbonCable
U14 U15 = Diode-0012: as U3 on sheet RibbonCable

## Sheet Power.SchDoc: M1 Test Fixture Board
size Legal; Author: Leo Buchman; Revision: B; SheetNumber: 4; SheetTotal: 4
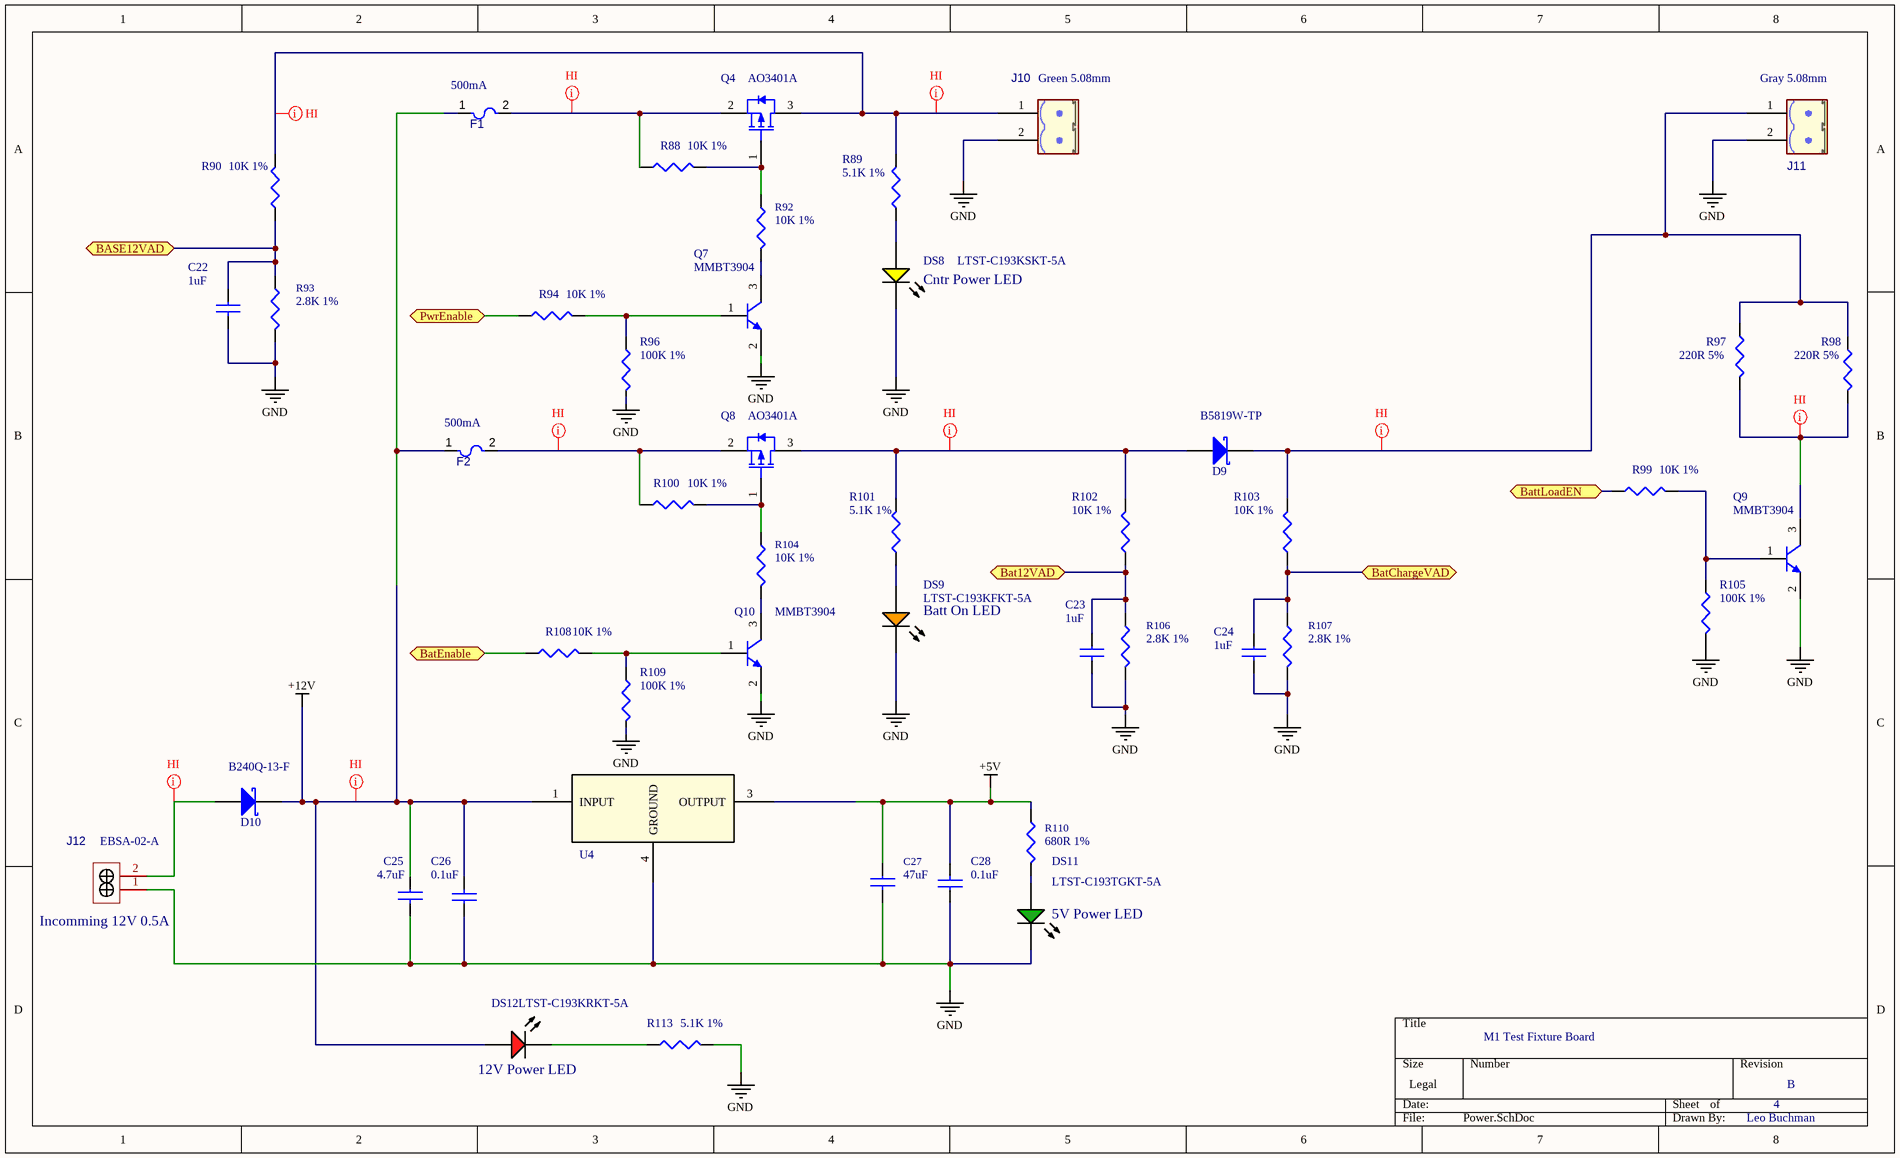
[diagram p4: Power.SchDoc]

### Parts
C22  1uF  [C0402]
C23  1uF  [C0402]
C24  1uF  [C0402]
C25  4.7uF  [C0603]
C26  0.1uF  [C0402]
C27  47uF  [C1210]
C28  0.1uF  [C0402]
D9  B5819W-TP  [MCC-SOD123_V]
D10  B240Q-13-F  [DIODE_DO214AA]
DS8  LTST-C193KSKT-5A  [LED-YELLOW_0603]
DS9  LTST-C193KFKT-5A  [LED-ORANGE_0603]
DS11  LTST-C193TGKT-5A  [LED-GREEN_0603]
DS12  LTST-C193KRKT-5A  [LED-RED_0603]
F1  500mA  [FUSE_F050-2]
F2  500mA  [FUSE_F050-2]
J10  Green 5.08mm  [Conn_5433668]
J11  Gray 5.08mm  [Conn_5442002]
J12  EBSA-02-A  [CONN-TH_2P-P3.50_JL15EDGRC-35002G01]
Q4  AO3401A  [AO-SOT-23-3L_V]
Q7  MMBT3904  [sot23-3]
Q8  AO3401A  [AO-SOT-23-3L_V]
Q9  MMBT3904  [sot23-3]
Q10  MMBT3904  [sot23-3]
R88  10K 1%  [R0402]
R89  5.1K 1%  [R0402]
R90  10K 1%  [R0402]
R92  10K 1%  [R0402]
R93  2.8K 1%  [R0402]
R94  10K 1%  [R0402]
R96  100K 1%  [R0402]
R97  220R 5%  [RESC6331X75N]
R98  220R 5%  [RESC6331X75N]
R99  10K 1%  [R0402]
R100  10K 1%  [R0402]
R101  5.1K 1%  [R0402]
R102  10K 1%  [R0402]
R103  10K 1%  [R0402]
R104  10K 1%  [R0402]
R105  100K 1%  [R0402]
R106  2.8K 1%  [R0402]
R107  2.8K 1%  [R0402]
R108  10K 1%  [R0402]
R109  100K 1%  [R0402]
R110  680R 1%  [R0402]
R113  5.1K 1%  [R0402]
U4  L7805CD2T-TR  [VREG_L7805ACD2T]  (value not drawn)

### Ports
BASE12VAD (bidir), Bat12VAD (bidir), BatChargeVAD (bidir), BatEnable (bidir), BattLoadEN (bidir), PwrEnable (bidir)

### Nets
+5V: C27.1 C28.2 R110.1 U4.3(OUTPUT)
+12V: C25.1 C26.2 D10.2(K) DS12.1(A) F1.1 F2.1 U4.1(INPUT)
GND: C22.2 C23.2 C24.2 C25.2 C26.1 C27.2 C28.1 DS8.2(K) DS9.2(K) DS11.2(K) J10.2 J11.2 J12.1 Q7.2(E) Q9.2(E) Q10.2(E) R93.2 R96.2 R105.2 R106.2 R107.2 R109.2 R113.2 U4.4(GROUND)
NetC22_1: C22.1 R90.1 R93.1 ; port BASE12VAD
NetC23_1: C23.1 R102.1 R106.1 ; port Bat12VAD
NetC24_1: C24.1 R103.1 R107.1 ; port BatChargeVAD
NetD9_1: D9.1(A) Q8.3(DRAIN) R101.2 R102.2
NetD9_2: D9.2(K) J11.1 R97.1 R98.1 R103.2
NetD10_1: D10.1(A) J12.2
NetDS8_1: DS8.1(A) R89.1
NetDS9_1: DS9.1(A) R101.1
NetDS11_1: DS11.1(A) R110.2
NetDS12_2: DS12.2(K) R113.1
NetF1_2: F1.2 Q4.2(SOURCE) R88.1
NetF2_2: F2.2 Q8.2(SOURCE) R100.1
NetJ10_1: J10.1 Q4.3(DRAIN) R89.2 R90.2
NetQ4_1: Q4.1(GATE) R88.2 R92.1
NetQ7_1: Q7.1(B) R94.2 R96.1
NetQ7_3: Q7.3(C) R92.2
NetQ8_1: Q8.1(GATE) R100.2 R104.1
NetQ9_1: Q9.1(B) R99.2 R105.1
NetQ9_3: Q9.3(C) R97.2 R98.2
NetQ10_1: Q10.1(B) R108.2 R109.1
NetQ10_3: Q10.3(C) R104.2
NetR94_1: R94.1 ; port PwrEnable
NetR99_1: R99.1 ; port BattLoadEN
NetR108_1: R108.1 ; port BatEnable

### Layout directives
net class HI: +12V, NetD9_1, NetD9_2, NetD10_1, NetF1_2, NetF2_2, NetJ10_1, NetQ9_3

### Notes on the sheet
- (near DS8) Cntr Power LED
- (near DS9) Batt On LED
- (near J12) Incomming 12V 0.5A
- (near DS11) 5V Power LED
- (near DS12) 12V Power LED

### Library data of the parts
C22-C24 = Cap-00003: as C2 on sheet Teensy
C25 = Cap-00001: CAP CER 4.7UF 16V X5R 0603; Manufacturer: Samsung; Manufacturer Part Number: CL10A475KO8NNNC; Material: Ceramic; Tolerance: 10%
C26 C28 = Cap-00005: as C1 on sheet Teensy
C27 = Cap-00004: CAP CER 47UF 16V X5R 1210; Manufacturer: Murata; Manufacturer Part Number: GRM32ER61C476ME15L; Tolerance: 20%; Dielectric Material: Ceramic
D9 = Diode-0002: DIODE SCHOTTKY 40V 1A SOD323; Manufacturer: MCC; Manufacturer Part Number: B5819W TP; Forward Current: 25mA; Forward Voltage: 600mV @ 1A; Color: Blue; Dominant Wavelength: 470nm; Lens Style: Diffused,Colorless,Rectangular,Clear; Luminous Intensity: 28.5mcd; Number of Elements: 1; Power Dissipation: 110W; Reverse Voltage: 5V; Test Current: 20mA; Viewing Angle: 120°
D10 = Diode-0008: Rectifier Diode Schottky 40V 2A Automotive 2-Pin SMB T/R; Manufacturer: Diodes; Manufacturer: MCC; Forward Current: 200mA; Forward Voltage: 800mV; Max Reverse Voltage (DC): 30V; Peak Non-Repetitive Surge Current: 600mA; Power Dissipation: 200mW; Max Reverse Current: 2uA; Capacitance: 10pF; Reverse Recovery Time: 5ns
DS8 = Diode-0006: LED Yellow CLEAR 0603 SMD; Manufacturer: Vishay Lite-On; Voltage Rating: 50 V; Power Rating: 75mW; Case\Package: 0603; Resistance: 390 Ohm; Forward Voltage: 2.0V; Lens Style: Diffused,Colorless,Rectangular; Viewing Angle: 130°; Forward Current: 30mA; Luminous Intensity: 45mcd; Dominant Wavelength: 594.5nm; Number of Elements: 1; Test Current: 5mA; Reverse Voltage: 5V; Lens Color: Colorless
DS9 = Diode-0004: LED Orange CLEAR 0603 SMD; Manufacturer: Vishay Lite-On; Manufacturer: Rohm; Viewing Angle: 130°; Forward Voltage: 2.0V; Forward (Drive) Current: 20mA; Intensity: 22mcd; Lens Style: Diffused,Colorless,Rectangular,Clear; Forward Current: 5mA; Luminous Intensity: 28.1mcd; Dominant Wavelength: 605nm; Number of Elements: 1; Lens Color: Colorless
DS11 = Diode-0007: LED Green CLEAR 0603 SMD; Manufacturer: Vishay Lite-On; Frequency: 400 KHz; Max Supply Voltage: 5.5 V; Access Time: 3500 ns; Clock Frequency: 100 KHz; Case\Package: SOIC; Density: 32 kb; Nominal Supply Current: 2 mA; Min Supply Voltage: 1.7 V; Max Reverse Voltage (DC): 40V; Average Rectified Current: 2A; Forward Voltage: 2.0V; Element Configuration: Single; Peak Non-Repetitive Surge Current: 50A; Lens Style: Diffused,Colorless,Rectangular; Viewing Angle: 130°; Forward Current: 5mA; Luminous Intensity: 280mcd; Dominant Wavelength: 535nm; Number of Elements: 1; Power Dissipation: 76mW; Reverse Voltage: 5V; Lens Color: Colorless; Max Reverse Current: 500uA
DS12 = Diode-0005: as DS5 on sheet InputOutput
F1 F2 = MF-MSMF050-2: 15VDC 500mA; Manufacturer: Bourns; Current Rating: 100A; Number of Terminals/Pins: 2; Trip Current: 1A; Voltage Rating: 15V; Resistance: 150mR; Power Dissipation: 800mW; Time to Trip: 0.15s; Aging: 1000 hr @ +85 °C (Passive); Approvals: UL,CSA,TUV
J10 = CON-0006: Pluggable Term Blocks BCH-508HS- 2 GN 5.08; Manufacturer: Phoenix Contact; Manufacturer Part Number: 5442002; ATTR: HEADER TERM BLK 5.08MM 2POS RTA GRAY; PKG: TB508HDR02_RTA; Connector Type: Screw; Number of Positions: 3; Pitch: 3.5mm; Current Rating: 13.5A; Voltage Rating: 200V; Gender: Male; Number of Levels: 1; Voltage: 300V; Approvals: UL,CSA,cULus,CB,EAC; Stripping Length: 5mm; Wire/Cable Gauge: 30AWG; Wire Gauge (Min): 16AWG
J11 = CON-0005: Pluggable Term Blocks BCH-508HS- 2 GR 5.08; Manufacturer: Phoenix Contact; Manufacturer Part Number: 5433668; PKG: TB508HDR02_RTA; ATTR: HEADER TERM BLK 5.08MM 2POS RTA GREEN; Current Rating: 12A; Voltage Rating: 320V; Number of Positions Per Level: 2; Number of Levels: 1
J12 = CON-0001: Conn Header Right angle 3.5 pitch 2P; Manufacturer: Adam Equipment; Connector Type: Male Pin; Number of Positions: 6; Pitch: 0.1inch
Q4 Q8 = Tran-0001: Mosfet P-channel 30V 4A SOT23-3; Manufacturer: Alpha & Omega Semiconductor; Manufacturer Part Number: AO3401AL; Output Power (Max): NotRequiredW; Power Dissipation: 350mW; Rad Hardened: No; Drain Efficiency: NotRequired%; Noise Figure: NotRequireddB; Frequency (Max): NotRequiredMHz; Number of  Elements: 1; Gate-Source Voltage (Max): ?12V; Channel Mode: Enhancement; Drain-Source On-Res: 0.044ohm; Type: PowerMOSFET; Polarity: NPN; Rds On Max: 50mR; Input Capacitance: 645pF; Max Power Dissipation: 1.4W; Collector Base Voltage (VCBO): 60V; Collector Emitter Breakdown Voltage: 40V; Collector Emitter Saturation Voltage: 300mV; Current Rating: 200mA; Element Configuration: Single; Emitter Base Voltage (VEBO): 6V; Frequency: 300MHz; hFE Min: 100
Q7 Q9 Q10 = Tran-0002: as Q1 on sheet Teensy
R88 R90 R92 R94 R99 R100 R102-R104 R108 = Res-00002: as R2 on sheet Teensy
R89 R101 R113 = Res-00004: as R6 on sheet Teensy
R93 R106 R107 = Res-00008: as R17 on sheet RibbonCable
R96 R105 R109 = Res-00003: as R9 on sheet Teensy
R97 R98 = Res-00005: Thick Film  220 OHM 5% 1W 2512; Manufacturer: Stackpole Electronics; Manufacturer Part Number: RMCF2512JT220R; Temperature Coefficient: 200ppm/°C
R110 = Res-00010: Thick Film 0402 680 Ohm 1% 0.063W(1/16W) ±100ppm/C Pad SMD Automotive T/R; Manufacturer: Stackpole Electronics; Manufacturer Part Number: RMCF0402FT680R; Max Power Dissipation: 63mW; Temperature Coefficient: 100ppm/°C; Power Rating: 62.5mW
U4 = LDO-0003: IC REG LDO 5V 1.5A D2PAK; Manufacturer 1: STMicroelectronics; Max Input Voltage: 35V; Number of Outputs: 1; Polarity: Positive; Quiescent Current: 8mA; Output Type: Fixed; Min Input Voltage: 10V; Dropout Voltage: 2V; Min Output Voltage: 4.8V; Power Supply Rejection Ratio (PSRR): 62dB

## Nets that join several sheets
+3.3V: Teensy (5 pins), RibbonCable (D5.2 D6.2), InputOutput (D7.2)
+5V: Teensy (7 pins), RibbonCable (25 pins), InputOutput (6 pins), Power (C27.1 C28.2 R110.1 U4.3)
GND: Teensy (35 pins), RibbonCable (38 pins), InputOutput (21 pins), Power (24 pins)
NetC22_1: Teensy (U2.15), Power (C22.1 R90.1 R93.1)
NetC23_1: Teensy (U2.41), Power (C23.1 R102.1 R106.1)
NetC24_1: Teensy (U2.23), Power (C24.1 R103.1 R107.1)
NetJ5_3: Teensy (U2.18), RibbonCable (J5.3 U3.4)
NetJ5_6: Teensy (U2.19), RibbonCable (J5.6 U3.5)
NetJ6_8: Teensy (Q13.3), InputOutput (J6.8)
NetR71_2: Teensy (U2.39), InputOutput (R71.2 R72.1)
NetR85_1: Teensy (U2.33), InputOutput (R85.1)
NetR94_1: Teensy (U2.20), Power (R94.1)
NetR99_1: Teensy (U2.21), Power (R99.1)
NetR108_1: Teensy (U2.22), Power (R108.1)
NetR118_1: Teensy (U2.14), RibbonCable (R118.1)
NetR119_1: Teensy (U2.16), RibbonCable (R119.1)
NetR120_1: Teensy (U2.17), InputOutput (R120.1)
NetU2_36: Teensy (U2.36), RibbonCable (U5.11 U6.11), InputOutput (U12.11)
NetU2_37: Teensy (U2.37), RibbonCable (U5.10 U6.10), InputOutput (U12.10)
NetU2_38: Teensy (U2.38), RibbonCable (U5.9 U6.9), InputOutput (U12.9)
